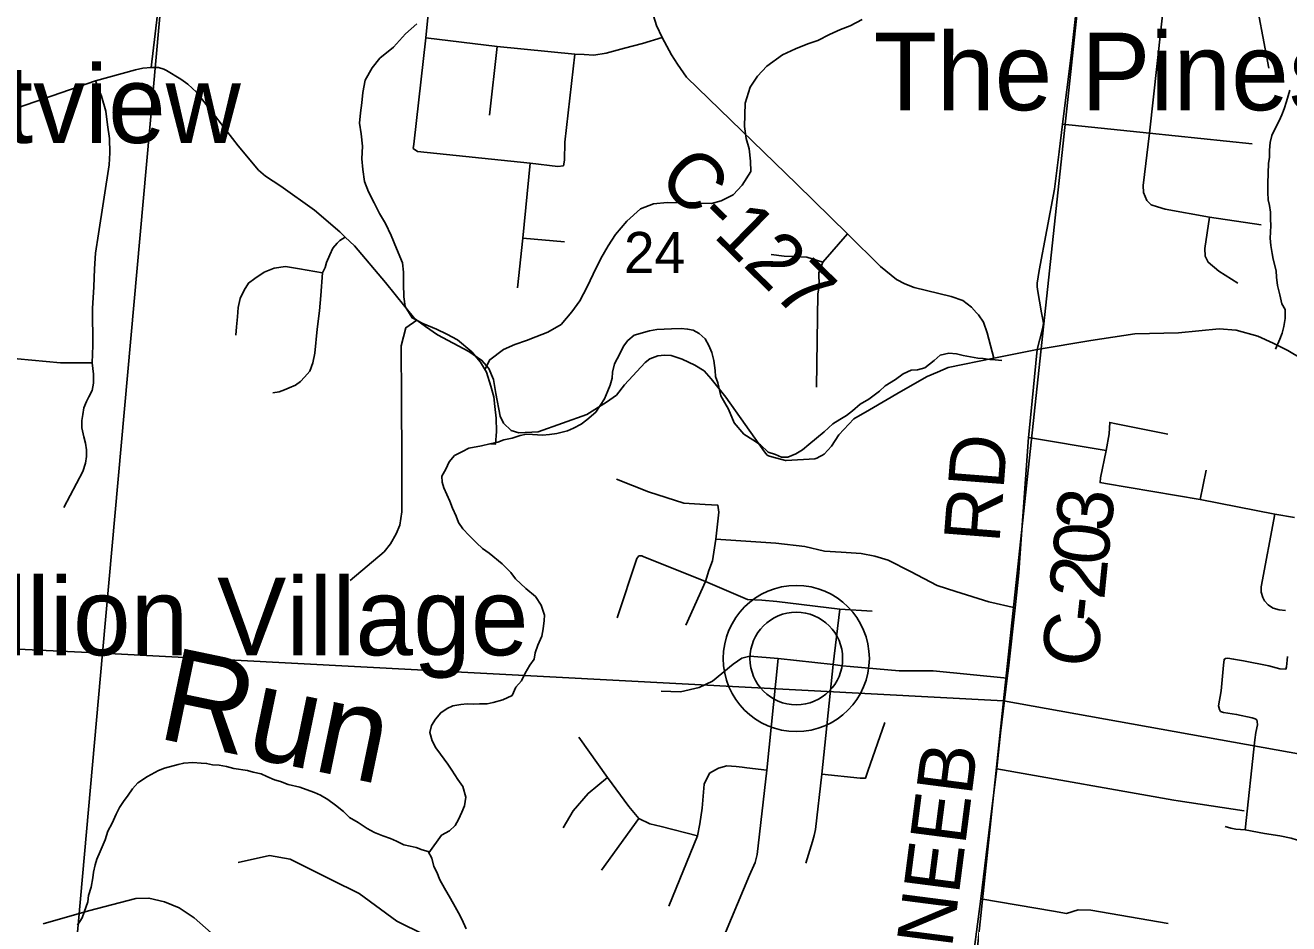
# Model space of a CAD drawing. Extents: x 0 to 34, y 0 to 22.
# Drawn here: x 5.631 to 6.917, y 16.185 to 17.1 of the extents above; entities that cross this region are included whole.
import ezdxf

# ---------------------------------------------------------------- set-up
doc = ezdxf.new("R2010")
doc.units = 0
for name, color, linetype in [('GM_X_Corporation', 7, 'Continuous'), ('GM_X_County_Road', 7, 'Continuous'), ('GM_X_County_Road_Text', 7, 'Continuous'), ('GM_X_Minor_River', 7, 'Continuous'), ('GM_X_Minor_River_Text', 7, 'Continuous'), ('GM_X_Section_Text', 7, 'Continuous'), ('GM_X_Township_Road', 7, 'Continuous'), ('GM_X_Unincorporated', 7, 'Continuous'), ('GM_X_Unincorporated_Location', 7, 'Continuous'), ('GM_X_Unincorporated_Text', 7, 'Continuous')]:
    doc.layers.add(name, color=color, linetype=linetype)

msp = doc.modelspace()

# ---------------------------------------------------------------- linework, layer by layer
at = {"layer": 'GM_X_Corporation'}
for points in [[(5.7989, 17.4561), (5.7092, 16.4608), (4.6148, 16.5127), (4.7377, 17.6243)], [(6.7271, 17.3517), (6.6267, 16.412), (5.7092, 16.4608), (5.7989, 17.4561)], [(7.7575, 17.2431), (7.6501, 16.2281), (6.6267, 16.412), (6.7271, 17.3517)], [(6.6267, 16.412), (6.5194, 15.3963), (5.7481, 15.5362), (5.7385, 15.5474), (5.73, 15.556), (5.7193, 15.5661), (5.7119, 15.5735), (5.7045, 15.5805), (5.6956, 15.5879), (5.6844, 15.5969), (5.6733, 15.6058), (5.6644, 15.6136), (5.6543, 15.6226), (5.6473, 15.6288), (5.6384, 15.6362), (5.6358, 15.6382), (5.7092, 16.4608)], [(7.6501, 16.2281), (7.5438, 15.2065), (6.5194, 15.3963), (6.6267, 16.412)]]:
    msp.add_lwpolyline(points, close=True, dxfattribs=at)
msp.add_lwpolyline([(4.6148, 16.5127), (5.7092, 16.4608), (5.6358, 15.6382)], dxfattribs=at)
at = {"layer": 'GM_X_County_Road'}
for points in [[(5.7588, 17.0569), (5.7793, 17.2289), (5.7863, 17.3229), (5.7905, 17.4119), (5.7946, 17.4559), (5.7951, 17.4608)], [(6.6432, 16.5578), (6.652, 16.6803), (6.6544, 16.7036), (6.6608, 16.7699), (6.6662, 16.791), (6.6671, 16.7962), (6.667, 16.7988), (6.6651, 16.8073), (6.6613, 16.8309), (6.6609, 16.8341), (6.6608, 16.8375), (6.663, 16.8502), (6.6784, 16.9333), (6.6831, 16.9712), (6.6866, 16.9992), (6.6955, 17.0691), (6.7092, 17.1947), (6.7305, 17.3523)], [(6.6168, 16.7609), (6.61, 16.7869), (6.6061, 16.7976), (6.6012, 16.805), (6.5991, 16.8073), (6.5939, 16.813), (6.585, 16.8199), (6.5733, 16.8237), (6.5355, 16.8329), (6.5262, 16.8367), (6.5175, 16.8413), (6.5015, 16.8545), (6.4676, 16.8878), (6.4161, 16.9383), (6.304, 17.0473), (6.2948, 17.0604), (6.2885, 17.07), (6.2791, 17.0875), (6.2733, 17.0999), (6.2669, 17.1205)], [(5.5961, 17.0068), (5.7022, 17.0433), (5.7428, 17.0546), (5.7505, 17.0563), (5.7588, 17.0569), (5.7664, 17.0571), (5.7718, 17.0553), (5.7746, 17.0539), (5.7889, 17.0452), (5.7962, 17.0399), (5.8049, 17.032), (5.8185, 17.0146), (5.8473, 16.9772), (5.868, 16.9525), (5.8751, 16.9463), (5.8908, 16.9361), (5.9251, 16.9118), (5.9508, 16.8896), (5.9565, 16.8842), (5.966, 16.8753), (5.9975, 16.8382), (6.027, 16.8015), (6.0292, 16.7999), (6.0382, 16.7933), (6.0505, 16.7847), (6.0824, 16.768), (6.0955, 16.7587), (6.1025, 16.7505), (6.1072, 16.7394), (6.1099, 16.725), (6.1143, 16.7021), (6.1176, 16.6948), (6.1254, 16.6875), (6.1333, 16.685), (6.153, 16.6861), (6.2023, 16.7036), (6.2223, 16.7161), (6.2327, 16.7234), (6.2406, 16.7339), (6.2619, 16.7566), (6.2665, 16.7602), (6.2746, 16.7634), (6.2816, 16.7642), (6.2882, 16.7636), (6.2995, 16.7599), (6.3123, 16.7539), (6.3217, 16.748), (6.3291, 16.7399), (6.3438, 16.7214), (6.3832, 16.6655), (6.386, 16.6624), (6.3873, 16.6615), (6.3906, 16.6605), (6.4045, 16.6569), (6.4054, 16.6567), (6.4346, 16.6587), (6.4366, 16.6593), (6.4397, 16.6609), (6.4415, 16.6618), (6.4441, 16.6634), (6.4516, 16.6716), (6.459, 16.6829), (6.4742, 16.6992), (6.4903, 16.7083), (6.5222, 16.727), (6.5487, 16.7423), (6.5594, 16.7469)], [(6.6168, 16.7609), (6.6608, 16.7699), (6.7156, 16.7789), (6.7602, 16.7859), (6.8046, 16.7868), (6.846, 16.7909), (6.8634, 16.7894), (6.8853, 16.7836), (6.901, 16.7764), (6.916, 16.7689), (6.9303, 16.7602)], [(6.5594, 16.7469), (6.5701, 16.7514), (6.6168, 16.7609)], [(6.6315, 16.4454), (6.6384, 16.5068), (6.6421, 16.5425), (6.6432, 16.5578)], [(6.6208, 16.3533), (6.6236, 16.3792), (6.6303, 16.4351), (6.6315, 16.4454)], [(6.6079, 16.0172), (6.6096, 16.028), (6.6076, 16.0398), (6.6067, 16.0578), (6.5964, 16.0864), (6.5935, 16.0997), (6.5922, 16.1142), (6.5931, 16.1303), (6.6034, 16.2106), (6.6129, 16.2888), (6.6196, 16.3429), (6.6208, 16.3533)], [(5.8476, 16.2475), (5.8792, 16.2545), (5.9003, 16.251), (5.9424, 16.2299), (5.9705, 16.2159), (6.0091, 16.1878), (6.0372, 16.1737), (6.0723, 16.1702), (6.118, 16.1702), (6.1593, 16.1701)], [(5.649, 16.1851), (5.6952, 16.1981), (5.7432, 16.2107), (5.7565, 16.2112), (5.7723, 16.2074), (5.7874, 16.2014), (5.8027, 16.1912), (5.8198, 16.176)]]:
    msp.add_lwpolyline(points, dxfattribs=at)
at = {"layer": 'GM_X_Minor_River'}
for points in [[(6.1043, 16.6739), (6.1094, 16.6735), (6.1105, 16.6864), (6.11, 16.7001), (6.1088, 16.7119), (6.1076, 16.7218), (6.1048, 16.7325), (6.1002, 16.7467), (6.094, 16.7571), (6.0852, 16.7675), (6.0707, 16.7797), (6.0599, 16.7856), (6.0493, 16.7905), (6.0355, 16.7965), (6.0246, 16.8021), (6.0173, 16.8137), (6.016, 16.8236), (6.0156, 16.8369), (6.0159, 16.8486), (6.0146, 16.8582), (6.0085, 16.8728), (6.0032, 16.8858), (5.9974, 16.8981), (5.9912, 16.9085), (5.9858, 16.9193), (5.98, 16.9304), (5.9761, 16.9408), (5.9745, 16.953), (5.9733, 16.964), (5.974, 16.9769), (5.9728, 16.9895), (5.9708, 17.0002), (5.9718, 17.0108), (5.9732, 17.021), (5.9743, 17.0316), (5.9768, 17.0441), (5.984, 17.0568), (5.9918, 17.0665), (6.0054, 17.0779), (6.0179, 17.0913), (6.0292, 17.1016)], [(6.0985, 16.7495), (6.1036, 16.7595), (6.1175, 16.7698), (6.129, 16.7748), (6.1409, 16.7791), (6.1505, 16.7826), (6.1628, 16.7876), (6.1762, 16.7953), (6.1872, 16.8083), (6.1951, 16.8195), (6.2026, 16.8337), (6.2087, 16.8465), (6.2167, 16.8626), (6.2242, 16.8753), (6.2317, 16.8869), (6.2431, 16.9007), (6.257, 16.9132), (6.2704, 16.9182), (6.2841, 16.9194), (6.297, 16.9191), (6.3084, 16.9196), (6.3183, 16.9189), (6.3293, 16.9187), (6.3392, 16.9211), (6.3515, 16.9272), (6.3605, 16.9372), (6.3692, 16.9511), (6.3691, 16.9617), (6.3675, 16.9743), (6.3647, 16.9846), (6.3628, 16.9968), (6.3634, 17.0207), (6.3687, 17.0369), (6.3762, 17.0481), (6.3856, 17.0585), (6.4014, 17.0699), (6.4149, 17.076), (6.4275, 17.081), (6.4375, 17.0846), (6.4494, 17.0907), (6.4606, 17.0958), (6.4705, 17.0993), (6.4828, 17.1058)], [(6.9033, 16.7702), (6.9077, 16.7803), (6.9101, 16.7864), (6.9121, 16.7932), (6.9134, 16.8015), (6.9132, 16.8107), (6.9099, 16.8164), (6.9077, 16.8256), (6.9056, 16.8351), (6.9043, 16.8435), (6.904, 16.85), (6.9011, 16.8618), (6.9001, 16.8675), (6.8987, 16.8759), (6.8981, 16.8831), (6.8982, 16.8892), (6.8987, 16.8961), (6.8985, 16.9025), (6.8982, 16.9098), (6.8972, 16.9166), (6.8961, 16.9223), (6.8955, 16.9299), (6.8957, 16.9391), (6.8964, 16.9592), (6.8973, 16.9656), (6.8974, 16.9729), (6.898, 16.9805), (6.8996, 16.9877), (6.904, 16.9971), (6.9072, 17.0027), (6.9099, 17.0088), (6.9123, 17.0148), (6.9148, 17.0224), (6.918, 17.0341)], [(6.0417, 16.2572), (6.0545, 16.2752), (6.0626, 16.2796), (6.0685, 16.2852), (6.0716, 16.2912), (6.0752, 16.2988), (6.078, 16.3052), (6.0793, 16.3139), (6.0761, 16.325), (6.0712, 16.3319), (6.0649, 16.3415), (6.0608, 16.3477), (6.0534, 16.3577), (6.0485, 16.3642), (6.0448, 16.3715), (6.0427, 16.3799), (6.0443, 16.3871), (6.0483, 16.3935), (6.0537, 16.3999), (6.0603, 16.4043), (6.0661, 16.4069), (6.0741, 16.4083), (6.0806, 16.4089), (6.0875, 16.4088), (6.0932, 16.4091), (6.1009, 16.4089), (6.107, 16.4103), (6.117, 16.4132), (6.1262, 16.4176), (6.1302, 16.4259), (6.1357, 16.4326), (6.1396, 16.4402), (6.1444, 16.4484), (6.1487, 16.4544), (6.1499, 16.4609), (6.1524, 16.4688), (6.1567, 16.4779), (6.158, 16.4855), (6.1589, 16.4938), (6.1594, 16.4995), (6.1558, 16.5094), (6.1502, 16.5183), (6.1404, 16.5264), (6.1296, 16.5365), (6.1251, 16.5427), (6.1161, 16.5516), (6.1029, 16.5625), (6.0961, 16.5671), (6.0901, 16.573), (6.0826, 16.5803), (6.0763, 16.5873), (6.0718, 16.5938), (6.0692, 16.6003), (6.0656, 16.6084), (6.063, 16.6153), (6.0568, 16.629), (6.055, 16.6348), (6.0547, 16.6409), (6.0587, 16.648), (6.0622, 16.6556), (6.0677, 16.6619), (6.0758, 16.666), (6.0823, 16.6693), (6.095, 16.6717), (6.1038, 16.6738), (6.1119, 16.6756), (6.118, 16.6778), (6.1264, 16.6795), (6.1345, 16.6824), (6.141, 16.6838), (6.1471, 16.6833), (6.1574, 16.6827), (6.1643, 16.6834), (6.172, 16.6844), (6.1827, 16.6869), (6.1889, 16.6898), (6.1966, 16.6938), (6.2024, 16.6983), (6.2117, 16.7061), (6.2203, 16.7196), (6.2239, 16.7279), (6.2263, 16.7336), (6.228, 16.7408), (6.2285, 16.7469), (6.2305, 16.7552), (6.2361, 16.7654), (6.2397, 16.7733), (6.244, 16.7789), (6.2506, 16.7845), (6.2663, 16.7888), (6.2736, 16.7902), (6.2885, 16.791), (6.2984, 16.7912), (6.3049, 16.7907), (6.3106, 16.7895), (6.3166, 16.7863), (6.323, 16.7809), (6.3267, 16.774), (6.3297, 16.7667), (6.3318, 16.7587), (6.3331, 16.7484)], [(6.3331, 16.7484), (6.3334, 16.7423), (6.3356, 16.7358), (6.3388, 16.7228), (6.3429, 16.7155), (6.3466, 16.709), (6.3524, 16.6952), (6.3621, 16.6837), (6.3712, 16.6778), (6.3791, 16.6727), (6.387, 16.6653), (6.3946, 16.6629), (6.4007, 16.6602), (6.4071, 16.6604), (6.4152, 16.6637), (6.4218, 16.6678), (6.4284, 16.673), (6.4439, 16.686), (6.4528, 16.6942), (6.4598, 16.6986), (6.4667, 16.7027), (6.4729, 16.7075), (6.4807, 16.7142), (6.4896, 16.7194), (6.5004, 16.7276), (6.5062, 16.7328), (6.5167, 16.7394), (6.5244, 16.745), (6.5325, 16.7487), (6.539, 16.7493), (6.5463, 16.7511), (6.556, 16.7585), (6.5622, 16.7641), (6.571, 16.7662), (6.5786, 16.7653), (6.5855, 16.7637), (6.5931, 16.7624), (6.6003, 16.7611), (6.606, 16.7606), (6.6125, 16.7598), (6.6182, 16.7593), (6.6247, 16.7588)], [(5.684, 16.1837), (5.6887, 16.1913), (5.6907, 16.1969), (5.6943, 16.2075), (5.6952, 16.2139), (5.6977, 16.2223), (5.6994, 16.2317), (5.7002, 16.2378), (5.7019, 16.245), (5.7035, 16.251), (5.7071, 16.2586), (5.7119, 16.2707), (5.7147, 16.2794), (5.7191, 16.2876), (5.7234, 16.2967), (5.7266, 16.3035), (5.7306, 16.3095), (5.7353, 16.3162), (5.74, 16.3226), (5.7454, 16.3286), (5.7551, 16.3349), (5.7663, 16.3412), (5.7724, 16.3437), (5.7862, 16.3473), (5.792, 16.3487), (5.8012, 16.3493), (5.8096, 16.3487), (5.8153, 16.3483), (5.8214, 16.347), (5.8282, 16.3465), (5.8355, 16.3452), (5.8431, 16.3432), (5.8571, 16.3411), (5.8628, 16.3394), (5.8708, 16.3378), (5.8765, 16.335), (5.8845, 16.3318), (5.8905, 16.3298), (5.8985, 16.327), (5.9103, 16.3241), (5.9168, 16.3217), (5.9251, 16.3189), (5.9312, 16.3162), (5.9387, 16.3115), (5.9466, 16.306), (5.9545, 16.2994), (5.9609, 16.2932), (5.9696, 16.2881), (5.9787, 16.2822), (5.9862, 16.2779), (5.9946, 16.2747), (6.0025, 16.2719), (6.0086, 16.2692), (6.0162, 16.2656), (6.0226, 16.264), (6.0287, 16.2627), (6.0348, 16.2603), (6.0409, 16.2587), (6.0445, 16.2518), (6.0467, 16.2434), (6.0496, 16.2376), (6.0529, 16.23), (6.0574, 16.2215), (6.0637, 16.2108), (6.0685, 16.2023), (6.0718, 16.1962), (6.0751, 16.1897), (6.0795, 16.1801)]]:
    msp.add_lwpolyline(points, dxfattribs=at)
at = {"layer": 'GM_X_Township_Road'}
for p, q in [((6.111, 17.0784), (6.1032, 17.0084)), ((6.1371, 16.8832), (6.1798, 16.8796)), ((6.8266, 16.6171), (6.833, 16.647)), ((6.8045, 16.3102), (6.8716, 16.3)), ((6.2172, 16.2398), (6.2553, 16.2922))]:
    msp.add_line(p, q, dxfattribs=at)
for points in [[(6.8889, 16.8969), (6.8362, 16.9046), (6.791, 16.9126), (6.7833, 16.915), (6.777, 16.9172), (6.7724, 16.9216), (6.769, 16.9296), (6.7686, 16.9369), (6.7751, 16.9901), (6.7949, 17.1694), (6.7973, 17.1983), (6.801, 17.2211), (6.8033, 17.2307), (6.8057, 17.2368), (6.8127, 17.2543), (6.8276, 17.2812), (6.8337, 17.295), (6.8354, 17.3017), (6.8403, 17.3406)], [(6.046, 17.1632), (6.0384, 17.0873), (6.0262, 16.9788), (6.0256, 16.9747), (6.0301, 16.9714), (6.1446, 16.9597), (6.173, 16.9562), (6.1786, 16.957), (6.1798, 16.9628), (6.18, 16.981), (6.1901, 17.0706)], [(6.7949, 17.1694), (6.856, 17.1619), (6.8621, 17.1591), (6.8684, 17.1555), (6.8728, 17.1515), (6.8774, 17.1464), (6.8806, 17.1408), (6.8966, 17.0562)], [(6.0384, 17.0873), (6.111, 17.0784), (6.1901, 17.0706), (6.1997, 17.0702), (6.2094, 17.0697), (6.2221, 17.0717), (6.2408, 17.0766), (6.259, 17.0813), (6.2791, 17.0875)], [(5.6701, 16.609), (5.6894, 16.6456), (5.6921, 16.654), (5.6931, 16.6609), (5.6931, 16.6677), (5.6921, 16.6744), (5.6903, 16.6811), (5.6884, 16.6901), (5.6882, 16.6976), (5.6892, 16.7038), (5.6904, 16.7103), (5.693, 16.7168), (5.6955, 16.7215), (5.6989, 16.728), (5.7, 16.7357), (5.7003, 16.7448), (5.6988, 16.7563), (5.6995, 16.774), (5.6991, 16.8117), (5.7006, 16.8338), (5.7012, 16.8519), (5.7022, 16.868), (5.7051, 16.8876), (5.7162, 16.9578), (5.7169, 16.9703), (5.7163, 16.9846), (5.7143, 16.9985), (5.7127, 17.0126), (5.7084, 17.0278), (5.7022, 17.0433)], [(6.6866, 16.9992), (6.7751, 16.9901), (6.8797, 16.9794)], [(6.1446, 16.9597), (6.1371, 16.8832), (6.1318, 16.8326)], [(6.8362, 16.9046), (6.8315, 16.8727), (6.8318, 16.8649), (6.8349, 16.8587), (6.8458, 16.8496), (6.8652, 16.8375)], [(5.8828, 16.7257), (5.8891, 16.7268), (5.8945, 16.7289), (5.8992, 16.7308), (5.9057, 16.7334), (5.9109, 16.7374), (5.9151, 16.7417), (5.9204, 16.7479), (5.9233, 16.7562), (5.9254, 16.7662), (5.928, 16.7906), (5.9303, 16.8093), (5.9317, 16.8248), (5.9332, 16.8479), (5.9359, 16.8532), (5.9375, 16.8584), (5.9406, 16.8664), (5.9437, 16.8732), (5.9483, 16.8782), (5.951, 16.8808), (5.9565, 16.8842)], [(6.4676, 16.8878), (6.4425, 16.8589), (6.4387, 16.8481), (6.4388, 16.8346), (6.4375, 16.8263), (6.4362, 16.7315)], [(6.3901, 16.8666), (6.4032, 16.865), (6.414, 16.8646), (6.4263, 16.8639), (6.4425, 16.8589)], [(5.8451, 16.7844), (5.8458, 16.793), (5.8466, 16.8033), (5.8474, 16.8128), (5.8495, 16.8217), (5.8534, 16.8302), (5.8578, 16.8375), (5.8643, 16.8421), (5.8738, 16.8487), (5.8841, 16.8526), (5.8955, 16.8543), (5.9099, 16.852), (5.9332, 16.8479)], [(6.0292, 16.7999), (6.0181, 16.7921), (6.0135, 16.7735), (6.0135, 16.7587), (6.0137, 16.7342), (6.0141, 16.6422), (6.0139, 16.6047), (6.0121, 16.591), (6.0084, 16.582), (6.0024, 16.5719), (5.9961, 16.564), (5.9616, 16.5348)], [(5.5038, 16.7618), (5.5212, 16.7641), (5.5418, 16.7674), (5.5564, 16.7676), (5.5933, 16.763), (5.6665, 16.7564), (5.6988, 16.7563)], [(6.731, 16.667), (6.734, 16.6841), (6.7347, 16.6956), (6.7413, 16.6941), (6.794, 16.6837)], [(6.652, 16.6803), (6.731, 16.667), (6.7253, 16.6392), (6.7248, 16.6344), (6.7305, 16.6334), (6.8266, 16.6171), (6.9028, 16.6021), (6.9229, 16.5988)], [(6.3032, 16.489), (6.3231, 16.5335), (6.3267, 16.5449), (6.3302, 16.5545), (6.3338, 16.5769), (6.3367, 16.6043), (6.3356, 16.6114), (6.3228, 16.6121), (6.3011, 16.6135), (6.2651, 16.6249), (6.2327, 16.6377)], [(6.9028, 16.6021), (6.8888, 16.5282), (6.8889, 16.5226), (6.8905, 16.5175), (6.8924, 16.514), (6.8961, 16.51), (6.8984, 16.5083), (6.901, 16.5065), (6.9071, 16.5047), (6.9137, 16.504)], [(6.6384, 16.5068), (6.6117, 16.5128), (6.5779, 16.5235), (6.5591, 16.5294), (6.5318, 16.5439), (6.5092, 16.5554), (6.4955, 16.5593), (6.4815, 16.5623), (6.4612, 16.5634), (6.4443, 16.5646), (6.4244, 16.5691), (6.3948, 16.5728), (6.3338, 16.5769)], [(6.493, 16.5034), (6.46, 16.5055), (6.3957, 16.5132), (6.3806, 16.5146), (6.3658, 16.5153), (6.3231, 16.5335), (6.2598, 16.559), (6.2583, 16.5596), (6.2568, 16.5599), (6.2554, 16.5596), (6.2542, 16.5585), (6.2534, 16.5572), (6.2334, 16.4966)], [(6.4252, 16.2467), (6.432, 16.2689), (6.4339, 16.275), (6.435, 16.2811), (6.4417, 16.3376), (6.453, 16.449), (6.46, 16.5055)], [(6.4628, 16.4479), (6.453, 16.449), (6.397, 16.4552), (6.3683, 16.4575), (6.3603, 16.4554), (6.3512, 16.4495), (6.3304, 16.4322), (6.3167, 16.4258), (6.2979, 16.4214), (6.2779, 16.4219)], [(6.397, 16.4552), (6.3855, 16.3415), (6.3757, 16.2557), (6.3736, 16.2474), (6.368, 16.2346), (6.3376, 16.1617)], [(6.8724, 16.2806), (6.8823, 16.3725), (6.8834, 16.3797), (6.8851, 16.3876), (6.8849, 16.3909), (6.8845, 16.3927), (6.8829, 16.3938), (6.8796, 16.3949), (6.8638, 16.3982), (6.8505, 16.4003), (6.8476, 16.4014), (6.8463, 16.4032), (6.8454, 16.4071), (6.8483, 16.4223), (6.8505, 16.4484), (6.8511, 16.4543), (6.8524, 16.4552), (6.8548, 16.4556), (6.8608, 16.4547), (6.8709, 16.4528), (6.8965, 16.4477), (6.9079, 16.4447), (6.9138, 16.4442), (6.9145, 16.4466), (6.9152, 16.4536), (6.9158, 16.4574)], [(6.6303, 16.4351), (6.555, 16.4426), (6.5204, 16.4427), (6.4706, 16.447), (6.4628, 16.4479)], [(6.4417, 16.3376), (6.4806, 16.3335), (6.4861, 16.3335), (6.4884, 16.3406), (6.5059, 16.3899)], [(6.1944, 16.3751), (6.2234, 16.3341), (6.245, 16.3045), (6.2553, 16.2922), (6.2664, 16.2867), (6.2781, 16.284), (6.3151, 16.2746)], [(6.2858, 16.2031), (6.3151, 16.2746), (6.3173, 16.2868), (6.3198, 16.3029), (6.3219, 16.3274), (6.3272, 16.3383), (6.3363, 16.3436), (6.3448, 16.3459), (6.3543, 16.3451), (6.3604, 16.3445)], [(6.3604, 16.3445), (6.3653, 16.344), (6.3855, 16.3415)], [(6.6196, 16.3429), (6.7998, 16.311), (6.8045, 16.3102)], [(6.1783, 16.2828), (6.1884, 16.3), (6.2037, 16.3179), (6.2234, 16.3341)], [(6.8522, 16.2841), (6.8581, 16.2826), (6.8632, 16.2815), (6.8724, 16.2806), (6.8921, 16.2771), (6.9079, 16.2745), (6.9195, 16.2723), (6.9257, 16.2703), (6.9318, 16.2672), (6.9367, 16.2622), (6.9419, 16.249), (6.9443, 16.2391), (6.9459, 16.2306), (6.9439, 16.2229), (6.9426, 16.2166), (6.9432, 16.2082), (6.9456, 16.2045), (6.9481, 16.2)], [(6.6034, 16.2106), (6.6776, 16.1979), (6.6908, 16.1954), (6.7024, 16.1992), (6.7154, 16.199), (6.7942, 16.1855)]]:
    msp.add_lwpolyline(points, dxfattribs=at)
at = {"layer": 'GM_X_Unincorporated'}
for radius in [0.0744, 0.0472]:
    msp.add_circle((6.4156, 16.4552), radius, dxfattribs=at)
at = {"layer": 'GM_X_Unincorporated_Location'}
msp.add_line((6.4156, 16.4552), (6.4156, 16.4552), dxfattribs=at)

# ---------------------------------------------------------------- texts
at = {"layer": 'GM_X_County_Road_Text'}
for s, height, rotation, p in [('C-127', 0.05682, 315.5865, (6.2728, 16.9414)), ('RD', 0.05682, 85.5636, (6.6223, 16.5719)), ('3', 0.0568, 84.3504, (6.7359, 16.5833)), ('0', 0.0568, 84.3347, (6.7324, 16.5487)), ('2', 0.0568, 84.2643, (6.729, 16.5141)), ('-', 0.0568, 83.9301, (6.7265, 16.4907)), ('C', 0.0568, 83.5847, (6.7213, 16.4443)), ('NEEB', 0.05682, 82.6474, (6.574, 16.1596))]:
    msp.add_text(s, height=height, rotation=rotation, dxfattribs=at).set_placement(p)
at = {"layer": 'GM_X_Minor_River_Text'}
msp.add_text('Run', height=0.0947, rotation=348.2363, dxfattribs=at).set_placement((5.7633, 16.3745))
at = {"layer": 'GM_X_Section_Text'}
msp.add_text('24', height=0.04186, rotation=0, dxfattribs=at).set_placement((6.2402, 16.8477))
at = {"layer": 'GM_X_Unincorporated_Text'}
for s, height, p in [('The Pines', 0.07898, (6.4943, 17.0135)), ('Mountview', 0.07898, (5.3452, 16.9802)), ('Cotillion Village', 0.078977, (5.421, 16.4585))]:
    msp.add_text(s, height=height, rotation=0, dxfattribs=at).set_placement(p)

doc.saveas('drawing.dxf')
